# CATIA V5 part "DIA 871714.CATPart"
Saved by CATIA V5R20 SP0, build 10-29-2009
Part number: DIA 871714
Revision: ANY
Definition: UNKNOWN
Nomenclature: DIA 871714
Source: Unknown
Bounding box of the stored display mesh (mm): x -4.35 to 4.35, y -17 to 0, z -4.35 to 4.35
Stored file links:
  C:\Users\Utente\Desktop\IO LAVORO\3D X SITO CF\CUMSA\3D files FA\FA 168712-21\DIA 871714.CATPart
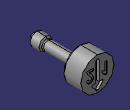
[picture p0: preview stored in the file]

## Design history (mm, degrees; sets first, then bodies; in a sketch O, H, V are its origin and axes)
Body1 "Cortar-Extruir2" (main body)
  Solid1: solid without history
